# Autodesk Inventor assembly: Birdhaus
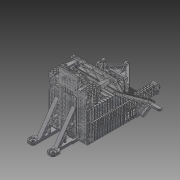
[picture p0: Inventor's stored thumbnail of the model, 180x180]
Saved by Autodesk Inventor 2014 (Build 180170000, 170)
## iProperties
Created: 2013-07
Part Number: Birdhaus
Document SubType Name: Assembly
Designer: Brent J. Rosenburgh
Author: Brent J. Rosenburgh
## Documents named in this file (7)
- E:\Documents\Inventor\BirdHouse\Birdhaus.iam
- E:\Documents\Inventor\BirdHouse\body.ipt
- E:\Documents\Inventor\BirdHouse\base.ipt
- E:\Documents\Inventor\BirdHouse\arm1.ipt
- E:\Documents\Inventor\BirdHouse\arm1_MIR.ipt
- E:\Documents\Inventor\BirdHouse\eave_perch.ipt
- E:\Documents\Inventor\BirdHouse\chimney.ipt
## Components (7 placed, 6 different names)
1. body:1 — Flush:1, Flush:3, Flush:4
2. base:1 — Flush:1, Flush:2
3. arm1:1 — Flush:2
4. arm1_MIR:1
5. eave_perch:1 — Flush:3
6. eave_perch:2
7. chimney:1
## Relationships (4: Flush 4)
- Flush:1: body:1 ↔ base:1
- Flush:2: base:1 ↔ arm1:1
- Flush:3: body:1 ↔ eave_perch:1
- Flush:4: body:1
